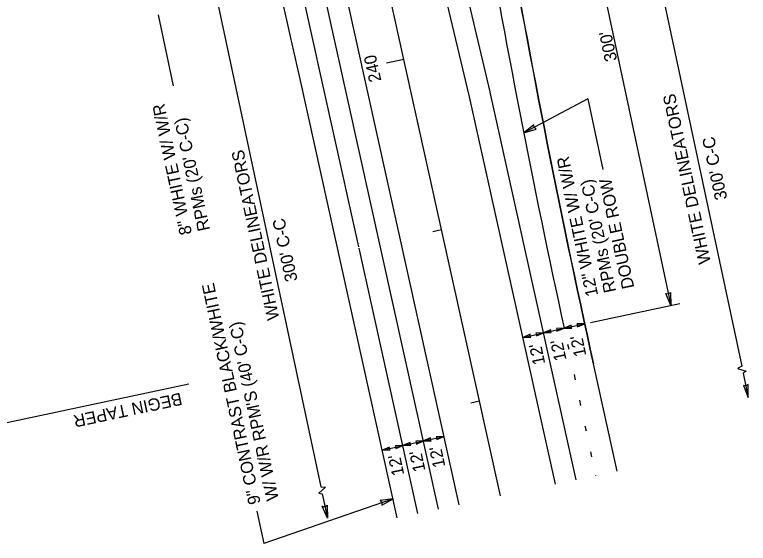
# Model space of a CAD drawing. Extents: x 578088 to 579220, y 1508751 to 1510400.
# Drawn here: x 578418.2 to 578835.8, y 1508791 to 1509092.1 of the extents above; entities that cross this region are included whole.
import ezdxf

# ---------------------------------------------------------------- set-up
doc = ezdxf.new("R2010")
doc.units = 0
for name, color, linetype in [('1', 7, 'Continuous'), ('18', 7, 'Continuous'), ('19', 7, 'Continuous'), ('2', 7, 'Continuous'), ('28', 7, 'Continuous'), ('41', 7, 'Continuous'), ('52', 7, 'Continuous')]:
    doc.layers.add(name, color=color, linetype=linetype)

msp = doc.modelspace()

# ---------------------------------------------------------------- linework, layer by layer
at = {"layer": '1'}
for p, q in [((578639.69, 1509066.69), (578362.17, 1510321.74)), ((578694.68, 1508818.01), (578639.69, 1509066.69)), ((578791.66, 1508926.54), (578788.78, 1508933.34)), ((578788.78, 1508933.34), (578790.27, 1508933.1)), ((578790.27, 1508933.1), (578791.47, 1508933.92)), ((578791.47, 1508933.92), (578791.66, 1508926.54)), ((578834.41, 1508880.72), (578832.97, 1508880.98)), ((578832.97, 1508880.98), (578835.8, 1508874.17)), ((578835.66, 1508881.55), (578834.41, 1508880.72)), ((578835.8, 1508874.17), (578835.66, 1508881.55))]:
    msp.add_line(p, q, dxfattribs=at)
at = {"layer": '18'}
for p, q in [((578659.48, 1508810.53), (578375.62, 1510094.27)), ((578688.9, 1509048.17), (578664.05, 1509152.58)), ((578688.94, 1509047.98), (578688.9, 1509048.17)), ((578737.77, 1508827.17), (578688.94, 1509047.98)), ((578647.72, 1508808.03), (578614.29, 1508959.23)), ((578747.52, 1508893.23), (578761.03, 1508832.11))]:
    msp.add_line(p, q, dxfattribs=at)
for radius, start, end in [(5729.75, 189.730019, 192.46846), (5741.58, 189.73613, 192.235242)]:
    msp.add_arc((584342.13, 1510130.3), radius, start, end, dxfattribs=at)
at = {"layer": '19'}
for p, q in [((578733.77, 1508901.38), (578733.14, 1508904.31)), ((578737.41, 1508884.21), (578736.79, 1508887.14)), ((578740.53, 1508869.54), (578739.91, 1508872.47)), ((578743.65, 1508854.86), (578743.03, 1508857.8)), ((578746.77, 1508840.19), (578746.15, 1508843.13)), ((578749.03, 1508829.56), (578749.03, 1508829.56)), ((578749.03, 1508829.54), (578749.03, 1508829.56))]:
    msp.add_line(p, q, dxfattribs=at)
at = {"layer": '2'}
for p, q in [((578677.17, 1509045.38), (578651.7, 1509152.41)), ((578725.98, 1508824.66), (578677.17, 1509045.38)), ((578761.19, 1508832.15), (578747.68, 1508893.27))]:
    msp.add_line(p, q, dxfattribs=at)
at = {"layer": '28'}
for p, q in [((578639.69, 1509066.69), (578629.93, 1509064.53)), ((578661.16, 1508969.59), (578656.28, 1508968.51)), ((578682.75, 1508871.95), (578677.87, 1508870.87))]:
    msp.add_line(p, q, dxfattribs=at)
at = {"layer": '41'}
for p, q in [((578671.2, 1508813.02), (578338.64, 1510317)), ((578614.13, 1508959.96), (578559.88, 1509205.29)), ((578635.99, 1508805.53), (578580.91, 1509054.61))]:
    msp.add_line(p, q, dxfattribs=at)
for centre, radius, start, end in [((574851.28, 1508229.92), 3819.72, 12.46859, 20.71859), ((584342.13, 1510130.3), 5729.58, 189.72994, 192.46846), ((584342.13, 1510130.3), 5729.58, 189.72994, 192.46846), ((584342.13, 1510130.3), 5729.58, 189.72994, 192.46846)]:
    msp.add_arc(centre, radius, start, end, dxfattribs=at)
at = {"layer": '52'}
for p, q in [((578760.74, 1509227.31), (578832.01, 1508892)), ((578729.16, 1509220.59), (578791.66, 1508926.54)), ((578513.15, 1509196.13), (578592.43, 1508823.18)), ((578499.91, 1509092.03), (578508.5, 1509051.63)), ((578744.44, 1509044.25), (578707.97, 1509024.83)), ((578744.44, 1509044.25), (578753.03, 1509003.85)), ((578713.74, 1509029.43), (578707.97, 1509024.83)), ((578707.97, 1509024.83), (578715.03, 1509027)), ((578713.89, 1509027.98), (578713.74, 1509029.43)), ((578715.03, 1509027), (578713.89, 1509027.98)), ((578745.93, 1508916.82), (578796.88, 1508927.65)), ((578719.25, 1508910.92), (578730.96, 1508913.51)), ((578730.96, 1508913.51), (578726.53, 1508913.39)), ((578726.89, 1508911.78), (578730.96, 1508913.51)), ((578730.96, 1508913.51), (578742.56, 1508916.07)), ((578735.03, 1508915.24), (578730.96, 1508913.51)), ((578730.96, 1508913.51), (578735.39, 1508913.63)), ((578734.89, 1508914.38), (578735.03, 1508915.24)), ((578735.39, 1508913.63), (578734.89, 1508914.38)), ((578742.56, 1508916.07), (578738.13, 1508915.95)), ((578738.13, 1508915.95), (578738.64, 1508915.2)), ((578738.49, 1508914.34), (578742.56, 1508916.07)), ((578738.64, 1508915.2), (578738.49, 1508914.34)), ((578707.57, 1508908.33), (578719.25, 1508910.92)), ((578711.65, 1508910.06), (578707.57, 1508908.33)), ((578711.5, 1508909.2), (578711.65, 1508910.06)), ((578719.25, 1508910.92), (578714.82, 1508910.8)), ((578714.82, 1508910.8), (578715.33, 1508910.05)), ((578715.18, 1508909.19), (578719.25, 1508910.92)), ((578715.33, 1508910.05), (578715.18, 1508909.19)), ((578723.33, 1508912.65), (578719.25, 1508910.92)), ((578719.25, 1508910.92), (578723.68, 1508911.04)), ((578723.18, 1508911.79), (578723.33, 1508912.65)), ((578723.68, 1508911.04), (578723.18, 1508911.79)), ((578726.53, 1508913.39), (578727.04, 1508912.64)), ((578727.04, 1508912.64), (578726.89, 1508911.78)), ((578707.57, 1508908.33), (578712, 1508908.45)), ((578712, 1508908.45), (578711.5, 1508909.2)), ((578832.01, 1508892), (578829.58, 1508890.65)), ((578829.58, 1508890.65), (578834.49, 1508889.08)), ((578832.01, 1508892), (578832.01, 1508892)), ((578834.49, 1508889.08), (578832.87, 1508887.96)), ((578832.87, 1508887.96), (578835.8, 1508874.17)), ((578364.55, 1508849.36), (578517.28, 1508881.82)), ((578650.92, 1508849.31), (578662.52, 1508851.88)), ((578654.99, 1508851.04), (578650.92, 1508849.31)), ((578654.84, 1508850.18), (578654.99, 1508851.04)), ((578662.52, 1508851.88), (578658.09, 1508851.76)), ((578658.09, 1508851.76), (578658.59, 1508851.01)), ((578658.45, 1508850.15), (578662.52, 1508851.88)), ((578658.59, 1508851.01), (578658.45, 1508850.15)), ((578627.53, 1508844.14), (578639.21, 1508846.72)), ((578639.21, 1508846.72), (578634.78, 1508846.6)), ((578635.14, 1508844.99), (578639.21, 1508846.72)), ((578639.21, 1508846.72), (578650.92, 1508849.31)), ((578643.28, 1508848.45), (578639.21, 1508846.72)), ((578639.21, 1508846.72), (578643.64, 1508846.84)), ((578643.14, 1508847.59), (578643.28, 1508848.45)), ((578643.64, 1508846.84), (578643.14, 1508847.59)), ((578650.92, 1508849.31), (578646.49, 1508849.19)), ((578646.49, 1508849.19), (578646.99, 1508848.44)), ((578646.85, 1508847.58), (578650.92, 1508849.31)), ((578646.99, 1508848.44), (578646.85, 1508847.58)), ((578650.92, 1508849.31), (578655.35, 1508849.43)), ((578655.35, 1508849.43), (578654.84, 1508850.18)), ((578631.6, 1508845.87), (578627.53, 1508844.14)), ((578627.53, 1508844.14), (578631.96, 1508844.26)), ((578631.46, 1508845.01), (578631.6, 1508845.87)), ((578631.96, 1508844.26), (578631.46, 1508845.01)), ((578634.78, 1508846.6), (578635.29, 1508845.86)), ((578635.29, 1508845.86), (578635.14, 1508844.99)), ((578595.19, 1508822.94), (578591.34, 1508819.5)), ((578592.43, 1508823.18), (578592.43, 1508823.18)), ((578592.43, 1508823.18), (578595.19, 1508822.94)), ((578591.34, 1508819.5), (578593.29, 1508819.14)), ((578593.29, 1508819.14), (578596.22, 1508805.35)), ((578633.58, 1508816.4), (578560.02, 1508791.01)), ((578633.58, 1508816.4), (578626.27, 1508815.36)), ((578626.27, 1508815.36), (578627.25, 1508814.22)), ((578627.17, 1508812.76), (578633.58, 1508816.4)), ((578627.25, 1508814.22), (578627.17, 1508812.76)), ((578556.11, 1508809.43), (578560.02, 1508791.01)), ((578596.22, 1508805.35), (578593.34, 1508812.15)), ((578593.34, 1508812.15), (578594.82, 1508811.9)), ((578594.82, 1508811.9), (578596.03, 1508812.72)), ((578596.03, 1508812.72), (578596.22, 1508805.35))]:
    msp.add_line(p, q, dxfattribs=at)

# ---------------------------------------------------------------- texts
at = {"layer": '18'}
for s, p in [('WHITE DELINEATORS', (578814.48, 1508950.93)), ("300' C-C", (578823.9, 1508987.33)), ("300' C-C", (578579.33, 1508940.81))]:
    msp.add_text(s, height=7, rotation=102, dxfattribs=at).set_placement(p)
at = {"layer": '28'}
msp.add_text('240', height=7, rotation=102.4686, dxfattribs=at).set_placement((578627.02, 1509054.53))
at = {"layer": '52'}
for s, rotation, p in [("300'", 102, (578761.19, 1509066.25)), ('8" WHITE W/ W/R', 102, (578519.2, 1508967.47)), ("RPMs (20' C-C)", 102, (578529.47, 1508969.65)), ('WHITE DELINEATORS', 102, (578568.96, 1508918.97)), ('12" WHITE W/ W/R', 102, (578750.38, 1508932.38)), ("RPMs (20' C-C)", 102, (578760.65, 1508934.56)), ('DOUBLE ROW', 102, (578770.93, 1508936.75)), ('9" CONTRAST BLACK/WHITE', 102, (578558.31, 1508813.95)), ("W/ W/R RPM'S (40' C-C)", 102, (578568.58, 1508816.13)), ("12'", 102, (578732.35, 1508895.69)), ("12'", 102, (578743.66, 1508898.09)), ("12'", 102, (578720.27, 1508893.42)), ('BEGIN TAPER', 192, (578512.67, 1508876.88)), ("12'", 102, (578652.09, 1508832.49)), ("12'", 102, (578663.4, 1508834.9)), ("12'", 102, (578640.01, 1508830.22))]:
    msp.add_text(s, height=7, rotation=rotation, dxfattribs=at).set_placement(p)

doc.saveas('drawing.dxf')
